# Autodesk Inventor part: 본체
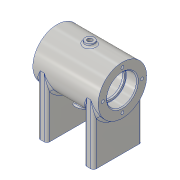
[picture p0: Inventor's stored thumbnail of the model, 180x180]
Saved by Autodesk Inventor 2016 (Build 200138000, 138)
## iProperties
Created: 2020-07
Part Number: 본체
Material: 알루미늄 6061
Document SubType Name: Modeling
Designer: user
Density: 2.7 g/cm^3
Appearance: 알루미늄 - 평지
Mass: 305.248 g
Surface Area: 357.567 cm^2
Volume: 113.055 cm^3
Author: user
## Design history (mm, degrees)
sketch "스케치1"
  geometry: L1 (-35, 0)-(35, 0); L2 (-35, 0)-(-35, 26); L3 (-35, 26)-(35, 26); L4 (35, 26)-(35, 0); L5 (-35, 16)-(-23, 16); L6 (-23, 16)-(-23, 14); L7 (-35, 0)-(-35, 16); L8 (-23, 14)-(-21, 14); L9 (-21, 21)-(21, 21); L10 (21, 21)-(21, 14); L11 (-21, 14)-(-21, 21); L12 (21, 14)-(23, 14); L13 (35, 16)-(23, 16); L14 (23, 16)-(23, 14); L15 (35, 0)-(35, 16); 1 further point
  constraints: 30 end point, 7 horizontal, 3 parallel, 3 perpendicular, 2 point on line, 2 vertical, 1 midpoint
  dimensions: "d0" = 70 distance of L1.start L1.end; "d1" = 35 distance of point (0, 0) L1.start; "d2" = 52 diameter of L3 L1; "d3" = 12 distance between parallel lines of L6 L2; "d5" = 42 distance between parallel lines of L10 L11; "d8" = 32 diameter of L5 L1; "d9" = 28 diameter of L8 L1; "d10" = 42 diameter of L9 L1; "d11" = 28 diameter of L12 L1; "d12" = 32 diameter of L13 L1
revolve "회전1" sketch "스케치1" stored, may be unused: angle "d13" = 90 deg
node "작업 평면2"
sketch "스케치3"
  geometry: L1 (0, -26)-(64, -26); L2 (0, 26)-(64, 26); L3 (64, -26)-(64, 26); C1 r 16 at (0, 0) reference; A1 r 26 centre (0, 0) between (0, -26) and (0, 26); 2 further points
  constraints: 6 end point, 2 horizontal, 2 point on circle, 1 centre point, 1 coincident, 1 parallel, 1 tangent, 1 vertical, 1 vertical alignment, 1 other
  dimensions: "d24" = 64 distance of L2.start L2.end
extrude "돌출2" join sketch "스케치3" distance "d26" = 10; taper "d27" = 0 deg
sketch "스케치4"
  geometry: L1 (60, 0)-(50, 0) reference; L2 (50, 0)-(50, 52) reference; L3 (50, 52)-(60, 52) reference; L4 (60, 52)-(60, 0) reference; L5 (10, 0)-(0, 0) reference; L6 (0, 0)-(0, 52) reference; L7 (0, 52)-(10, 52) reference; L8 (10, 52)-(10, 0) reference; L9 (5, 52)-(5, 0); 3 further points
  constraints: 2 end point, 2 midpoint, 2 point on line
  dimensions: "d28" = 20 vertical distance of point (30, 26) point (5, 46); "d29" = 20 vertical distance of point (30, 26) point (5, 6)
hole "구멍1" sketch "스케치4" at (5, 46), (5, 6) diameter "d30" = 4.134; stored, may be unused: countersink angle "d34" = 90 deg, drill point angle "d36" = 118 deg; dims "d31" = 8, "d32" = 4, "d33" = 2, "d35" = 10
node "작업 평면3"
sketch "스케치5"
  geometry: C1 r 5 at (0, 0); 1 further point
  constraints: 1 centre point, 1 coincident
  dimensions: "d38" = 10 diameter of C1
extrude "돌출3" join sketch "스케치5" stored distance "d39" = 10; taper "d40" = 0 deg
hole "구멍2" diameter "d43" = 5.188; stored, may be unused: countersink angle "d47" = 90 deg, drill point angle "d49" = 118 deg; dims "d41" = 10, "d42" = 10, "d44" = 12, "d45" = 4, "d46" = 2, "d48" = 16
sketch "스케치6" dims "d50" = 42
  geometry: L1 (0, 0)-(0, 21); C1 r 26 at (0, 0) reference; C2 r 16 at (0, 0) reference; 1 further point
  constraints: 2 end point, 1 coincident, 1 vertical, 1 vertical alignment, 2 other
hole "구멍3" sketch "스케치6" at (0, 21) diameter "d51" = 3.242; stored, may be unused: countersink angle "d55" = 90 deg, drill point angle "d57" = 118 deg; dims "d52" = 8, "d53" = 4, "d54" = 2, "d56" = 10
sketch "스케치7"
  geometry: L1 (29, -5)-(25.515, -5) reference; L2 (25.515, 5)-(29, 5) reference; L3 (29, 5)-(29, 2.594) reference; L4 (29, 2.594)-(20.839, 2.594) reference; L5 (20.839, -2.594)-(29, -2.594) reference; L6 (29, -2.594)-(29, -5) reference; L7 (0, 0)-(-21, 0); L8 (-21.613, 7.866)-(-27.251, 9.919); L9 (-27.251, 9.919)-(-25.199, 15.557); L10 (-25.199, 15.557)-(-18.812, 13.232); L11 (0, 0)-(7.182, 19.734); L12 (8.893, 24.432)-(9.196, 25.267); L13 (-21.613, 7.866)-(-18.812, 13.232); A1 r 26 centre (0, 0) between (25.515, 5) and (25.515, -5) reference; A2 r 21 centre (0, 0) between (20.839, 2.594) and (20.839, -2.594) reference; 1 further point
  constraints: 15 end point, 3 perpendicular, 3 point on circle, 1 horizontal, 1 parallel
  dimensions: "d62" = 20 deg angle of L8 L7; "d64" = 6 distance of L8.end L9.end; "d65" = 29 distance of point (0, 0) L8.end; "d68" = 29 distance between parallel lines of L9 L11
revolve "회전2" sketch "스케치7" stored, may be unused: angle "d78" = 90 deg
hole "구멍4" diameter "d81" = 5.188; stored, may be unused: countersink angle "d85" = 90 deg, drill point angle "d87" = 118 deg; dims "d79" = 10, "d80" = 10, "d82" = 12, "d83" = 4, "d84" = 2, "d86" = 10
fillet "모깎기1" dims "d88" = 0.3
fillet "모깎기2" dims "d89" = 2
fillet "모깎기3" dims "d90" = 3
chamfer "모따기1" distance "d91" = 1; stored, may be unused: second distance "d92" = 2, angle "d93" = 45 deg
fillet "모깎기4" dims "d94" = 2
fillet "모깎기5" dims "d95" = 3
fillet "모깎기6" dims "d96" = 3
node "작업 평면4"
sketch "스케치8"
  geometry: L1 (35, 26)-(-35, 26) reference; L2 (-35, 26)-(-35, -26) reference; 2 further points
  constraints: 1 other
  dimensions: "d98" = 26 distance from line of point (0, 0) L1; "d99" = 35 distance from line of point (0, 0) L2
feature "엠보싱1" sketch "스케치8" dims "d0" = 70, "d1" = 35, "d2" = 52, "d3" = 12, "d5" = 42, "d8" = 32, "d9" = 28, "d10" = 42, "d11" = 28, "d12" = 32, "d24" = 64, "d100" = 0.5, "d101" = 0
node "솔리드1"
mirror "대칭1"
mirror "대칭2"
pattern_circular "원형 패턴1" dims angle "d59" = 360 deg
mirror "대칭3"
node "절단 모서리 투영1"
node "절단 모서리 투영2"
node "절단 모서리 투영3"
node "절단 모서리 투영4"
other parameters: "d37" = 29, "d63" = 29, "d97" = -26
